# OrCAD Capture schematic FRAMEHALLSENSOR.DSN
size B; title: HALL SENSOR BOARD; note: tbd
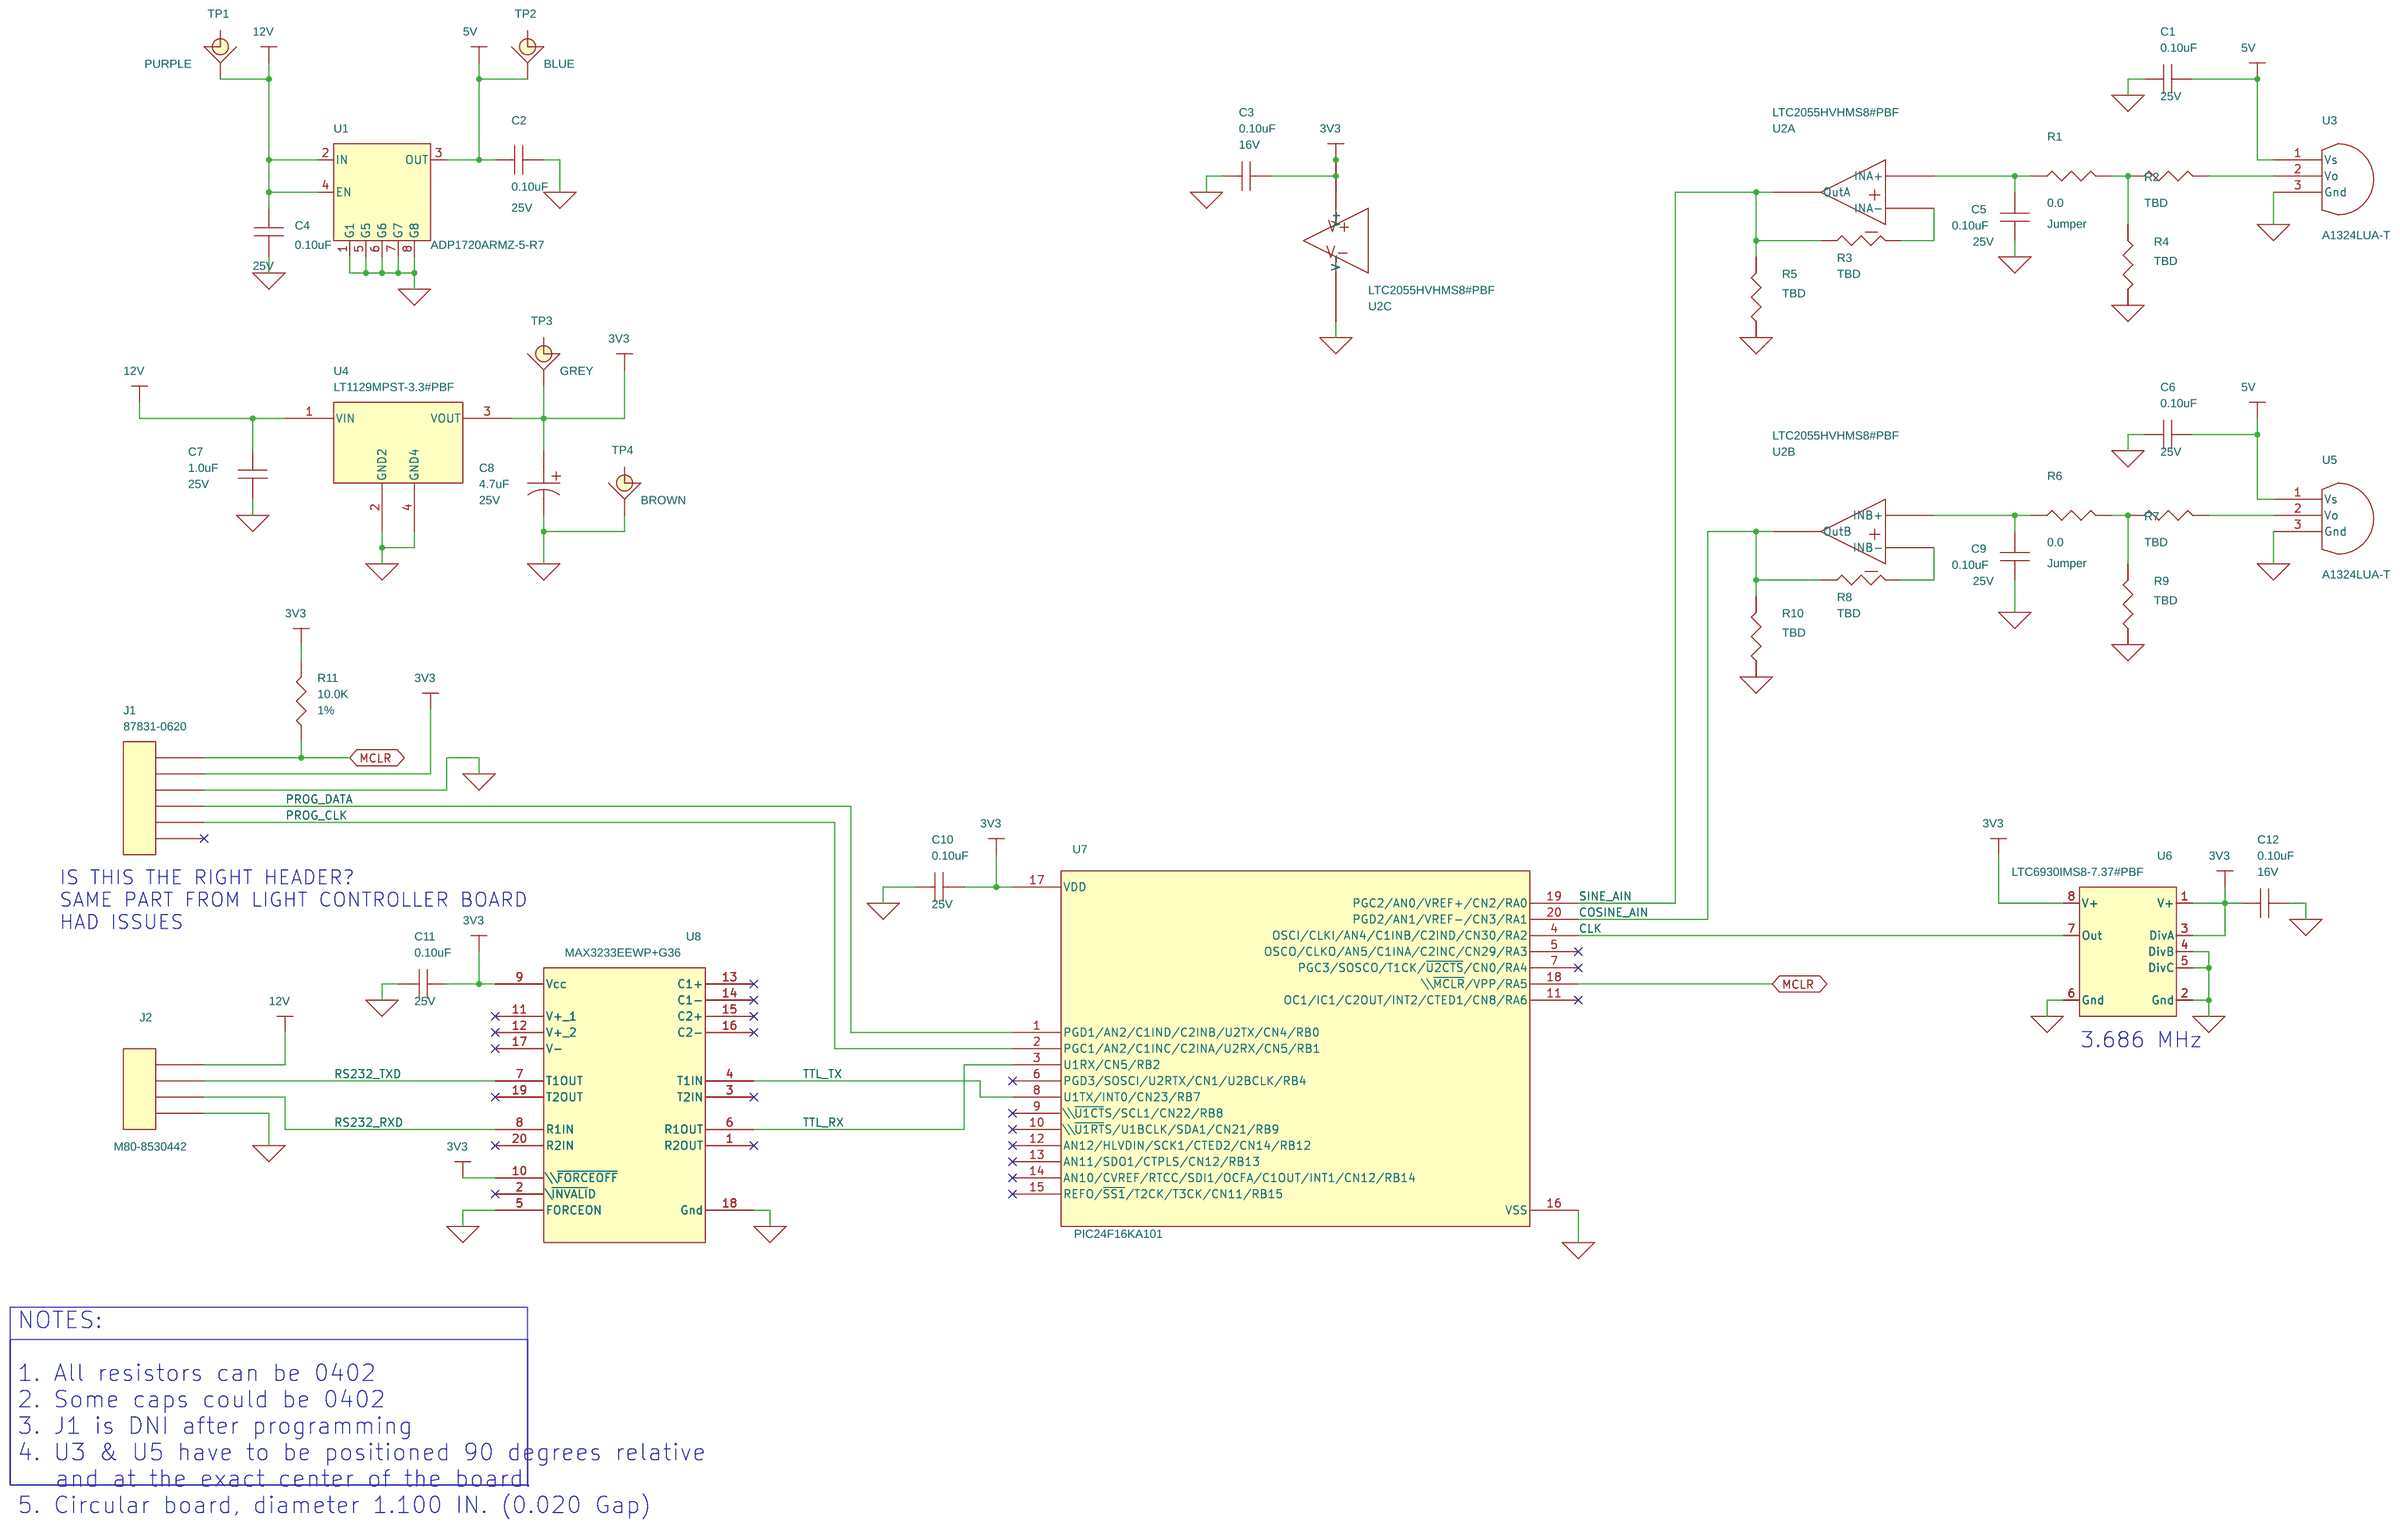
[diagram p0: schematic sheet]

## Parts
C1  0.10uF  [CAPC1608X87N]
C2  0.10uF  [CAPC2012X100N]
C3  0.10uF  [CAPC1608X87N]
C4  0.10uF  [CAPC2012X100N]
C5  0.10uF  [CAPC1608X87N]
C6  0.10uF  [CAPC1608X87N]
C7  1.0uF  [CAPC3216X175N]
C8  4.7uF  [CAPMP3528X210N]
C9  0.10uF  [CAPC1608X87N]
C10  0.10uF  [CAPC1608X87N]
C11  0.10uF  [CAPC1608X87N]
C12  0.10uF  [CAPC1608X87N]
J1  87831-0620  [MOLEX_87831-0620]
J2  M80-8530442  [HARWIN_M80-8530442]
R1  0.0  [RESC1608X50N]
R2  TBD  [RESC1608X50N]
R3  TBD  [RESC1608X50N]
R4  TBD  [RESC1608X50N]
R5  TBD  [RESC1608X50N]
R6  0.0  [RESC1608X50N]
R7  TBD  [RESC1608X50N]
R8  TBD  [RESC1608X50N]
R9  TBD  [RESC1608X50N]
R10  TBD  [RESC1608X50N]
R11  10.0K  [RESC1608X50N]
TP1  PURPLE  [TP_KEYSTONE_5000s_MINI]
TP2  BLUE  [TP_KEYSTONE_5000s_MINI]
TP3  GREY  [TP_KEYSTONE_5000s_MINI]
TP4  BROWN  [TP_KEYSTONE_5000s_MINI]
U1  ADP1720ARMZ-5-R7  [SOP65P490X110-8N]
U2  LTC2055HVHMS8#PBF  [SOP65P490X110-8L30N]  (sections A,B,C)
U3  A1324LUA-T  [UNASSIGNED]
U4  LT1129MPST-3.3#PBF  [SOT230P700X180-4L20N]
U5  A1324LUA-T  [UNASSIGNED]
U6  LTC6930IMS8-7.37#PBF  [SOP65P490X110-8L30N]
U7  PIC24F16KA101
U8  MAX3233EEWP+G36  [SOIC127P1032X265-20N]

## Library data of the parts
C1 C5 C6 C9-C11 = CAP: CAP CER 0.1UF 25V 10% X7R 0603; CLASS: DISCRETE; Dielectric Type: Ceramic; Manufacturer: Kemet; Manufacturer PN: C0603C104K3RACTU; PART_NUMBER: C0603C104K3RAC; Package Size: 0603; Rated Voltage: 25V; Temperature Coefficient: X7R; Tolerance: 10%
C2 C4 = CAP: CLASS: DISCRETE; Dielectric Type: Ceramic; Manufacturer: Kemet; Manufacturer PN: C0805C104K3RAC; PART_NUMBER: C0805C104K3RAC; Package Size: 0805; Rated Voltage: 25V; Temperature Coefficient: X7R; Tolerance: 10%
C3 C12 = CAP: CAP, CER, 0.10uF, 16V, 10%, X7R, 0603; CLASS: DISCRETE; Dielectric Type: Ceramic; Manufacturer: Kemet; Manufacturer PN: C0603C104K4RAC; PART_NUMBER: C0603C104K4RAC; Package Size: 0603; Rated Voltage: 16V; Temperature Coefficient: X7R; Tolerance: 10%
C7 = CAP: CAP, CER, 1.0uF, 25V, 10%, X7R, 1206; CLASS: DISCRETE; Dielectric Type: Ceramic; Manufacturer: Kemet; Manufacturer PN: C1206C105K3RACTU; PART_NUMBER: C1206C105K3RAC; Package Size: 1206; Rated Voltage: 25V; Temperature Coefficient: X7R; Tolerance: 10%
C8 = CAP_P: CLASS: DISCRETE; Dielectric Type: Tantalum MnO2; Manufacturer: AVX Corporation; Manufacturer PN: TPSB475K025R0700; PART_NUMBER: TPSB475K025R0700; Package Size: 3528-21; Rated Voltage: 25V; Tolerance: 10%
J1 = CON6: CONN HEADER 6POS 2MM VERT GOLD; CLASS: IO; Manufacturer: Molex Connector Corporation; Package Size: 0.141" (3.60mm)
J2 = CON4: CONN HDR 2MM DUAL W/LATCH 4POS; CLASS: IO; Manufacturer: Harwin Inc
R1 R6 = RES: RES 0.0 OHM 1/10W 0603 SMD; CLASS: DISCRETE; Manufacturer: Vishay/Dale; Manufacturer PN: CRCW06030000Z0EA; PART_NUMBER: CRCW06030000Z0EA; Package Size: 0603 (1608 Metric); Rated Power: 0.1W, 1/10W; Tolerance: Jumper
R2-R5 R7-R10 = RES: TO BE DETERMINED, HEIGHT 0.5mm; CLASS: DISCRETE; PART_NUMBER: TBD_R0603; Package Size: 0603
R11 = RES: CLASS: DISCRETE; Manufacturer: Vishay; Manufacturer PN: CRCW060310K0FKEA; PART_NUMBER: CRCW060310K0FKEA; Package Size: 0603; Rated Power: 0.1W; Temperature Coefficient: 100ppm/K; Tolerance: 1%
TP1 = TESTPOINT: TEST POINT PC MINI T/H PURPLE; CLASS: DISCRETE; Manufacturer: Keystone Electronics; Manufacturer PN: 5119; PART_NUMBER: 5119
TP2 = TESTPOINT: TEST POINT PC MINIATURE T/H BLUE; CLASS: DISCRETE; Manufacturer: Keystone Electronics; Manufacturer PN: 5117; PART_NUMBER: 5117
TP3 = TESTPOINT: TEST POINT PC MINIATURE T/H GREY; CLASS: DISCRETE; Manufacturer: Keystone Electronics; Manufacturer PN: 5118; PART_NUMBER: 5118
TP4 = TESTPOINT: TEST POINT PC MINIATURE T/H BRWN; CLASS: DISCRETE; Manufacturer: Keystone Electronics; Manufacturer PN: 5115; PART_NUMBER: 5115
U1 = ADP1720_FIXED: IC REG LDO HV 50MA 5.0V 8-MSOP; CLASS: IC; Manufacturer: Analog Devices Inc; Package Size: 8-TSSOP, 8-MSOP (0.118", 3.00mm Width)
U2 = LTC2055_MS8: IC OPAMP CHOPPER 500KHZ 8MSOP; CLASS: IC; Manufacturer: Linear Technology; Package Size: 8-TSSOP, 8-MSOP (0.118", 3.00mm Width); Supply Voltage: 2.7 V - 11 V, 1.35 V - 5.5 V
U3 U5 = AD22103: IC HALL EFFECT SENSOR 3SIP RATIOMETRIC; CLASS: IC; Depth_Tested: 2000m; Manufacturer: Allegro MicroSystems, LLC; PART_NUMBER: TMP-2065; Package Size: 3-SSIP; Supply Voltage: 4.5 V - 5.5 V
U4 = LT1129_ST: IC REG LDO 3.3V 0.7A SOT223; CLASS: IC; Manufacturer: Linear Technology; Package Size: TO-261-4, TO-261AA
U6 = LTC6930: IC OSC SILICON 7.3728MHZ 8-MSOP; CLASS: IC; Manufacturer: Linear Technology; Package Size: 8-TSSOP, 8-MSOP (0.118", 3.00mm Width); Supply Voltage: 1.7 V - 5.5 V
U7 = PIC24FXXKA101
U8 = MAX3233E: IC TXRX RS232 DUAL250KBPS 20SOIC; CLASS: IC; Manufacturer: Maxim Integrated Products; PART_NUMBER: MAX3233EEWP_G36; Package Size: 20-SOIC (0.295", 7.50mm Width); Supply Voltage: 3 V ~ 3.6 V

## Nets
3V3: C3.2 C8.1 C10.2 C11.1 C12.1 J1.2 R11.2 TP3.1(TP) U2.8(V+) U4.3(VOUT) U6.1(V+) U6.3(DivA) U6.8(V+) U7.17(VDD) U8.9(Vcc) U8.10(\\~{FORCEOFF})
5V: C1.2 C2.1 C6.2 TP2.1(TP) U1.3(OUT) U3.1(Vs) U5.1(Vs)
12V: C4.1 C7.1 J2.1 TP1.1(TP) U1.2(IN) U1.4(EN) U4.1(VIN)
GND_SIGNAL: C1.1 C2.2 C3.1 C4.2 C5.1 C6.1 C7.2 C8.2 C9.1 C10.1 C11.2 C12.2 J1.3 J2.4 R4.1 R5.1 R9.1 R10.1 TP4.1(TP) U1.1(G1) U1.5(G5) U1.6(G6) U1.7(G7) U1.8(G8) U2.4(V-) U3.3(Gnd) U4.2(GND2) U4.4(GND4) U5.3(Gnd) U6.2(Gnd) U6.4(DivB) U6.5(DivC) U6.6(Gnd) U7.16(VSS) U8.5(FORCEON) U8.18(Gnd)
CLK: U6.7(Out) U7.4(OSCI/CLKI/AN4/C1INB/C2IND/CN30/RA2)
COSINE_AIN: R8.1 R10.2 U2.7(OutB) U7.20(PGD2/AN1/VREF-/CN3/RA1)
MCLR: J1.1 R11.1 U7.18(\\~{MCLR}/VPP/RA5)
PROG_CLK: J1.5 U7.2(PGC1/AN2/C1INC/C2INA/U2RX/CN5/RB1)
PROG_DATA: J1.4 U7.1(PGD1/AN2/C1IND/C2INB/U2TX/CN4/RB0)
RS232_RXD: J2.3 U8.8(R1IN)
RS232_TXD: J2.2 U8.7(T1OUT)
SINE_AIN: R3.1 R5.2 U2.1(OutA) U7.19(PGC2/AN0/VREF+/CN2/RA0)
TTL_RX: U7.3(U1RX/CN5/RB2) U8.6(R1OUT)
TTL_TX: U7.8(U1TX/INT0/CN23/RB7) U8.4(T1IN)
N08487: R2.2 U3.2(Vo)
N08491: R1.2 R2.1 R4.2
N08495: R7.2 U5.2(Vo)
N08499: R6.2 R7.1 R9.2
N08743: C9.2 R6.1 U2.5(INB+)
N08748: R8.2 U2.6(INB-)
N08822: C5.2 R1.1 U2.3(INA+)
N08834: R3.2 U2.2(INA-)

Not connected (* = marked no-connect by the designer): J1 6*; U7 5(OSCO/CLKO/AN5/C1INA/C2INC/CN29/RA3)* 6(PGD3/SOSCI/U2RTX/CN1/U2BCLK/RB4)* 7(PGC3/SOSCO/T1CK/~{U2CTS}/CN0/RA4)* 9(\\~{U1CT}S/SCL1/CN22/RB8)* 10(\\~{U1RT}S/U1BCLK/SDA1/CN21/RB9)* 11(OC1/IC1/C2OUT/INT2/CTED1/CN8/RA6)* 12(AN12/HLVDIN/SCK1/CTED2/CN14/RB12)* 13(AN11/SDO1/CTPLS/CN12/RB13)* 14(AN10/CVREF/RTCC/SDI1/OCFA/C1OUT/INT1/CN12/RB14)* 15(REFO/~{SS1}/T2CK/T3CK/CN11/RB15)*; U8 1(R2OUT)* 2(\~{INVALI}D)* 3(T2IN)* 11(V+_1)* 12(V+_2)* 13(C1+)* 14(C1-)* 15(C2+)* 16(C2-)* 17(V-)* 19(T2OUT)* 20(R2IN)*

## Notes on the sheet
- IS THIS THE RIGHT HEADER?
  SAME PART FROM LIGHT CONTROLLER BOARD
  HAD ISSUES
- 3.686 MHz
- NOTES:
  1. All resistors can be 0402
  2. Some caps could be 0402
  3. J1 is DNI after programming
  4. U3 & U5 have to be positioned 90 degrees relative
     and at the exact center of the board.
  5. Circular board, diameter 1.100 IN. (0.020 Gap)
